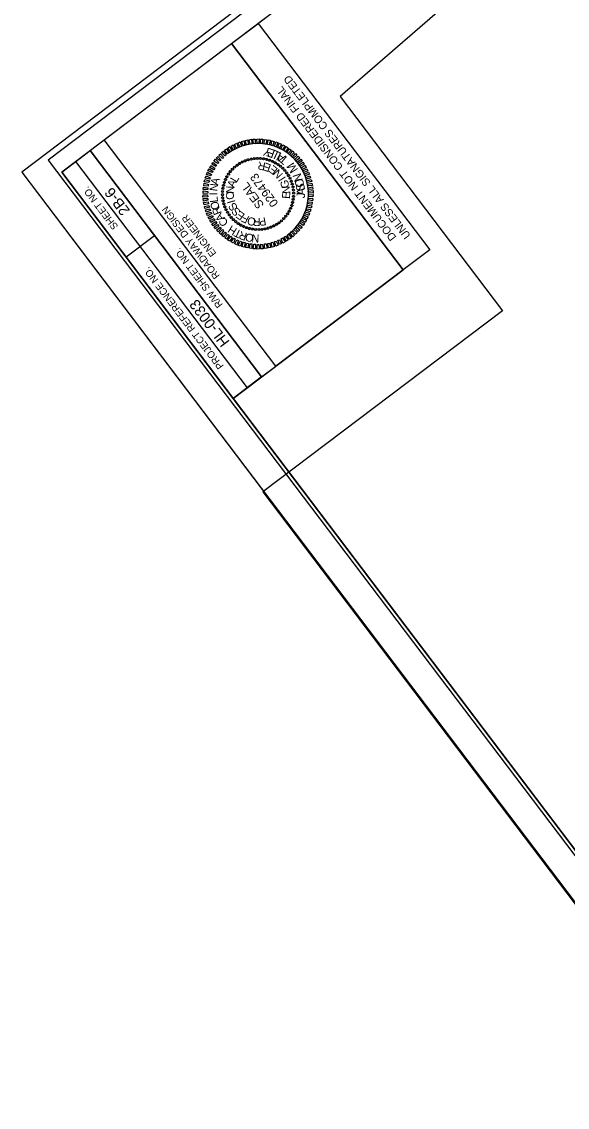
# Model space of a CAD drawing. Extents: x 2046295 to 2051060, y 758814 to 763808.
# Drawn here: x 2046295.2 to 2046525.7, y 759223.6 to 759682.5 of the extents above; entities that cross this region are included whole.
import ezdxf

# ---------------------------------------------------------------- set-up
doc = ezdxf.new("R2010")
doc.units = 0
for name, color, linetype in [('Exist Mkg Skp Wht', 7, 'Continuous'), ('Old_Level_2', 7, 'Continuous'), ('Scratch_Level_0', 7, 'Continuous'), ('Sheet Clip Boundary CELL', 7, 'Continuous'), ('Sheet Cutting Line CELL', 7, 'Continuous'), ('Sheet Data Field CELL', 7, 'Continuous'), ('Sheet Plan CELL', 7, 'Continuous'), ('Sheet Plot Border Inside CELL', 7, 'Continuous'), ('Sheet Plot Border Outside CELL', 7, 'Continuous'), ('Sheet Sticker Exception Certification CELL', 7, 'Continuous')]:
    doc.layers.add(name, color=color, linetype=linetype)

msp = doc.modelspace()

# ---------------------------------------------------------------- linework, layer by layer
at = {"layer": 'Old_Level_2'}
for p, q in [((2046386.22, 759621.85), (2046386.22, 759621.85)), ((2046387.32, 759622.57), (2046387.32, 759622.57)), ((2046388.48, 759623.18), (2046388.48, 759623.18)), ((2046389.64, 759623.73), (2046389.64, 759623.73)), ((2046390.9, 759624.15), (2046390.9, 759624.15)), ((2046392.19, 759624.45), (2046392.19, 759624.45)), ((2046393.48, 759624.67), (2046393.48, 759624.67)), ((2046394.79, 759624.73), (2046394.79, 759624.73)), ((2046396.12, 759624.72), (2046396.12, 759624.72)), ((2046397.41, 759624.56), (2046397.41, 759624.56)), ((2046398.72, 759624.31), (2046398.72, 759624.31)), ((2046399.95, 759623.93), (2046399.95, 759623.93)), ((2046401.19, 759623.44), (2046401.19, 759623.44)), ((2046402.37, 759622.87), (2046402.37, 759622.87)), ((2046403.48, 759622.2), (2046403.48, 759622.2)), ((2046382.57, 759618.07), (2046382.57, 759618.07)), ((2046383.35, 759619.11), (2046383.35, 759619.11)), ((2046384.26, 759620.1), (2046384.26, 759620.1)), ((2046385.18, 759621.03), (2046385.18, 759621.03)), ((2046404.53, 759621.41), (2046404.53, 759621.41)), ((2046405.52, 759620.51), (2046405.52, 759620.51)), ((2046406.44, 759619.59), (2046406.44, 759619.59)), ((2046407.26, 759618.55), (2046407.26, 759618.55)), ((2046407.99, 759617.44), (2046407.99, 759617.44)), ((2046380.45, 759613.31), (2046380.45, 759613.31)), ((2046380.84, 759614.54), (2046380.84, 759614.54)), ((2046381.33, 759615.78), (2046381.33, 759615.78)), ((2046381.9, 759616.96), (2046381.9, 759616.96)), ((2046408.6, 759616.29), (2046408.6, 759616.29)), ((2046409.14, 759615.12), (2046409.14, 759615.12)), ((2046409.57, 759613.86), (2046409.57, 759613.86)), ((2046380.04, 759609.38), (2046380.04, 759609.38)), ((2046380.05, 759610.71), (2046380.05, 759610.71)), ((2046380.09, 759608.07), (2046380.09, 759608.07)), ((2046380.21, 759611.99), (2046380.21, 759611.99)), ((2046395.09, 759609.68), (2046395.09, 759609.68)), ((2046409.86, 759612.58), (2046409.86, 759612.58)), ((2046410.09, 759611.29), (2046410.09, 759611.29)), ((2046410.13, 759608.65), (2046410.13, 759608.65)), ((2046410.14, 759609.97), (2046410.14, 759609.97)), ((2046380.32, 759606.77), (2046380.32, 759606.77)), ((2046380.61, 759605.49), (2046380.61, 759605.49)), ((2046381.04, 759604.23), (2046381.04, 759604.23)), ((2046408.85, 759603.58), (2046408.85, 759603.58)), ((2046409.34, 759604.81), (2046409.34, 759604.81)), ((2046409.73, 759606.05), (2046409.73, 759606.05)), ((2046409.98, 759607.36), (2046409.98, 759607.36)), ((2046381.58, 759603.06), (2046381.58, 759603.06)), ((2046382.2, 759601.91), (2046382.2, 759601.91)), ((2046382.92, 759600.8), (2046382.92, 759600.8)), ((2046383.74, 759599.77), (2046383.74, 759599.77)), ((2046405.92, 759599.25), (2046405.92, 759599.25)), ((2046406.83, 759600.24), (2046406.83, 759600.24)), ((2046407.61, 759601.28), (2046407.61, 759601.28)), ((2046408.28, 759602.39), (2046408.28, 759602.39)), ((2046384.66, 759598.85), (2046384.66, 759598.85)), ((2046385.65, 759597.94), (2046385.65, 759597.94)), ((2046386.7, 759597.15), (2046386.7, 759597.15)), ((2046387.81, 759596.48), (2046387.81, 759596.48)), ((2046388.99, 759595.91), (2046388.99, 759595.91)), ((2046390.23, 759595.42), (2046390.23, 759595.42)), ((2046391.46, 759595.04), (2046391.46, 759595.04)), ((2046392.78, 759594.79), (2046392.78, 759594.79)), ((2046394.06, 759594.64), (2046394.06, 759594.64)), ((2046395.39, 759594.62), (2046395.39, 759594.62)), ((2046396.7, 759594.68), (2046396.7, 759594.68)), ((2046398, 759594.9), (2046398, 759594.9)), ((2046399.28, 759595.2), (2046399.28, 759595.2)), ((2046400.54, 759595.62), (2046400.54, 759595.62)), ((2046401.7, 759596.17), (2046401.7, 759596.17)), ((2046402.86, 759596.78), (2046402.86, 759596.78)), ((2046403.97, 759597.51), (2046403.97, 759597.51)), ((2046405, 759598.33), (2046405, 759598.33))]:
    msp.add_line(p, q, dxfattribs=at)
for points in [[(2046386.05, 759629.02), (2046385.12, 759630.65), (2046386.06, 759631.1), (2046386.7, 759629.21)], [(2046387.43, 759629.58), (2046386.62, 759631.3), (2046387.54, 759631.73), (2046388.08, 759629.77)], [(2046388.85, 759630.09), (2046388.16, 759631.9), (2046389.14, 759632.15), (2046389.56, 759630.21)], [(2046390.27, 759630.41), (2046389.7, 759632.31), (2046390.71, 759632.51), (2046390.98, 759630.57)], [(2046391.73, 759630.76), (2046391.3, 759632.58), (2046392.31, 759632.78), (2046392.4, 759630.82)], [(2046393.19, 759630.97), (2046392.9, 759632.85), (2046393.93, 759632.88), (2046393.91, 759630.91)], [(2046394.69, 759630.97), (2046394.53, 759632.88), (2046395.57, 759632.95), (2046395.38, 759631.01)], [(2046396.15, 759630.94), (2046396.14, 759632.89), (2046397.16, 759632.84), (2046396.83, 759630.94)], [(2046397.69, 759630.8), (2046397.75, 759632.76), (2046398.75, 759632.58), (2046398.36, 759630.7)], [(2046399.12, 759630.64), (2046399.38, 759632.49), (2046400.39, 759632.35), (2046399.8, 759630.44)], [(2046400.59, 759630.25), (2046400.96, 759632.14), (2046401.95, 759631.88), (2046401.24, 759630.03)], [(2046402, 759629.88), (2046402.54, 759631.69), (2046403.47, 759631.41), (2046402.68, 759629.57)], [(2046403.39, 759629.28), (2046404.01, 759631.14), (2046404.96, 759630.69), (2046404.02, 759629.04)], [(2046380.02, 759624.72), (2046378.5, 759626.02), (2046379.26, 759626.7), (2046380.52, 759625.25)], [(2046381.06, 759625.73), (2046379.69, 759627.14), (2046380.46, 759627.8), (2046381.59, 759626.21)], [(2046382.23, 759626.66), (2046380.98, 759628.16), (2046381.8, 759628.77), (2046382.81, 759627.09)], [(2046383.45, 759627.54), (2046382.32, 759629.13), (2046383.14, 759629.68), (2046384.06, 759627.93)], [(2046384.69, 759628.29), (2046383.67, 759629.93), (2046384.56, 759630.45), (2046385.35, 759628.6)], [(2046404.74, 759628.69), (2046405.5, 759630.47), (2046406.4, 759629.98), (2046405.36, 759628.32)], [(2046406.04, 759628.01), (2046406.96, 759629.69), (2046407.79, 759629.19), (2046406.64, 759627.52)], [(2046407.31, 759627.13), (2046408.33, 759628.77), (2046409.11, 759628.19), (2046407.86, 759626.76)], [(2046408.49, 759626.22), (2046409.62, 759627.86), (2046410.4, 759627.18), (2046408.99, 759625.81)], [(2046409.62, 759625.27), (2046410.87, 759626.81), (2046411.53, 759626.08), (2046410.13, 759624.75)], [(2046377.24, 759621.22), (2046375.52, 759622.21), (2046376.06, 759623.04), (2046377.56, 759621.84)], [(2046378.1, 759622.48), (2046376.39, 759623.59), (2046377.07, 759624.33), (2046378.48, 759623.02)], [(2046379.03, 759623.63), (2046377.44, 759624.79), (2046378.14, 759625.55), (2046379.42, 759624.16)], [(2046410.64, 759624.23), (2046411.97, 759625.65), (2046412.68, 759624.91), (2046411.14, 759623.71)], [(2046411.66, 759623.13), (2046413.13, 759624.42), (2046413.7, 759623.61), (2046412.07, 759622.53)], [(2046412.51, 759621.96), (2046414.06, 759623.14), (2046414.64, 759622.33), (2046412.92, 759621.37)], [(2046374.69, 759615.9), (2046372.79, 759616.31), (2046373.14, 759617.29), (2046374.92, 759616.53)], [(2046375.2, 759617.27), (2046373.33, 759617.85), (2046373.7, 759618.84), (2046375.42, 759617.96)], [(2046375.78, 759618.68), (2046373.93, 759619.39), (2046374.43, 759620.26), (2046376.01, 759619.32)], [(2046376.44, 759619.94), (2046374.66, 759620.81), (2046375.19, 759621.7), (2046376.79, 759620.58)], [(2046413.34, 759620.71), (2046414.97, 759621.79), (2046415.42, 759620.89), (2046413.68, 759620.06)], [(2046414.02, 759619.42), (2046415.71, 759620.36), (2046416.19, 759619.48), (2046414.38, 759618.79)], [(2046414.68, 759618), (2046416.41, 759618.93), (2046416.84, 759617.98), (2046414.94, 759617.4)], [(2046415.24, 759616.61), (2046416.99, 759617.38), (2046417.31, 759616.45), (2046415.45, 759615.98)], [(2046374.07, 759612.99), (2046372.17, 759613.17), (2046372.31, 759614.17), (2046374.18, 759613.64)], [(2046374.3, 759614.48), (2046372.39, 759614.76), (2046372.65, 759615.75), (2046374.52, 759615.17)], [(2046415.62, 759615.21), (2046417.55, 759615.8), (2046417.77, 759614.91), (2046415.87, 759614.53)], [(2046415.98, 759613.79), (2046417.85, 759614.26), (2046418.07, 759613.27), (2046416.12, 759613.07)], [(2046416.27, 759612.27), (2046418.12, 759612.66), (2046418.25, 759611.63), (2046416.32, 759611.6)], [(2046373.86, 759608.5), (2046371.83, 759608.29), (2046371.87, 759609.29), (2046373.74, 759609.24)], [(2046373.83, 759610.02), (2046371.85, 759609.91), (2046371.9, 759610.93), (2046373.82, 759610.73)], [(2046373.88, 759611.49), (2046371.9, 759611.53), (2046372.04, 759612.54), (2046373.9, 759612.22)], [(2046416.33, 759610.85), (2046418.35, 759611.07), (2046418.32, 759610.06), (2046416.44, 759610.11)], [(2046416.35, 759609.33), (2046418.34, 759609.44), (2046418.28, 759608.42), (2046416.36, 759608.62)], [(2046373.92, 759607.08), (2046372.06, 759606.69), (2046371.93, 759607.72), (2046373.86, 759607.75)], [(2046374.2, 759605.56), (2046372.34, 759605.09), (2046372.11, 759606.09), (2046374.06, 759606.29)], [(2046374.56, 759604.14), (2046372.64, 759603.55), (2046372.42, 759604.44), (2046374.31, 759604.82)], [(2046415.88, 759604.87), (2046417.79, 759604.59), (2046417.53, 759603.6), (2046415.66, 759604.18)], [(2046416.11, 759606.36), (2046418.01, 759606.19), (2046417.88, 759605.18), (2046416, 759605.71)], [(2046416.3, 759607.86), (2046418.28, 759607.82), (2046418.14, 759606.81), (2046416.28, 759607.13)], [(2046374.94, 759602.74), (2046373.19, 759601.97), (2046372.87, 759602.9), (2046374.73, 759603.37)], [(2046375.5, 759601.36), (2046373.77, 759600.42), (2046373.34, 759601.38), (2046375.24, 759601.95)], [(2046376.16, 759599.94), (2046374.47, 759598.99), (2046373.99, 759599.87), (2046375.8, 759600.56)], [(2046376.84, 759598.64), (2046375.21, 759597.56), (2046374.76, 759598.46), (2046376.5, 759599.29)], [(2046413.74, 759599.41), (2046415.52, 759598.54), (2046414.99, 759597.65), (2046413.39, 759598.77)], [(2046414.4, 759600.67), (2046416.25, 759599.96), (2046415.75, 759599.09), (2046414.17, 759600.04)], [(2046414.99, 759602.09), (2046416.85, 759601.51), (2046416.48, 759600.51), (2046414.76, 759601.39)], [(2046415.49, 759603.45), (2046417.39, 759603.04), (2046417.04, 759602.06), (2046415.26, 759602.82)], [(2046377.67, 759597.39), (2046376.12, 759596.22), (2046375.55, 759597.02), (2046377.26, 759597.99)], [(2046378.52, 759596.23), (2046377.06, 759594.93), (2046376.48, 759595.74), (2046378.11, 759596.82)], [(2046379.54, 759595.12), (2046378.21, 759593.7), (2046377.5, 759594.44), (2046379.04, 759595.64)], [(2046380.56, 759594.08), (2046379.32, 759592.54), (2046378.65, 759593.28), (2046380.05, 759594.6)], [(2046410.16, 759594.64), (2046411.68, 759593.33), (2046410.92, 759592.65), (2046409.66, 759594.11)], [(2046411.15, 759595.72), (2046412.75, 759594.56), (2046412.04, 759593.8), (2046410.76, 759595.2)], [(2046412.08, 759596.88), (2046413.79, 759595.76), (2046413.11, 759595.02), (2046411.71, 759596.33)], [(2046412.94, 759598.13), (2046414.67, 759597.14), (2046414.12, 759596.32), (2046412.62, 759597.51)], [(2046381.69, 759593.13), (2046380.56, 759591.49), (2046379.78, 759592.18), (2046381.19, 759593.54)], [(2046382.87, 759592.22), (2046381.85, 759590.58), (2046381.07, 759591.16), (2046382.32, 759592.6)], [(2046384.14, 759591.34), (2046383.22, 759589.67), (2046382.39, 759590.17), (2046383.54, 759591.83)], [(2046385.44, 759590.67), (2046384.68, 759588.89), (2046383.78, 759589.37), (2046384.82, 759591.03)], [(2046386.79, 759590.07), (2046386.17, 759588.21), (2046385.23, 759588.66), (2046386.16, 759590.31)], [(2046388.19, 759589.47), (2046387.64, 759587.66), (2046386.71, 759587.94), (2046387.5, 759589.78)], [(2046402.75, 759589.77), (2046403.56, 759588.05), (2046402.64, 759587.62), (2046402.1, 759589.58)], [(2046404.13, 759590.33), (2046405.06, 759588.7), (2046404.12, 759588.25), (2046403.48, 759590.14)], [(2046405.49, 759591.06), (2046406.51, 759589.42), (2046405.62, 759588.9), (2046404.83, 759590.75)], [(2046406.73, 759591.81), (2046407.86, 759590.22), (2046407.04, 759589.67), (2046406.12, 759591.43)], [(2046407.95, 759592.69), (2046409.2, 759591.19), (2046408.38, 759590.58), (2046407.37, 759592.26)], [(2046409.13, 759593.62), (2046410.49, 759592.21), (2046409.72, 759591.55), (2046408.59, 759593.14)], [(2046389.59, 759589.11), (2046389.22, 759587.21), (2046388.23, 759587.47), (2046388.94, 759589.33)], [(2046391.06, 759588.71), (2046390.8, 759586.86), (2046389.79, 759587), (2046390.38, 759588.91)], [(2046392.49, 759588.56), (2046392.44, 759586.59), (2046391.43, 759586.78), (2046391.82, 759588.65)], [(2046394.03, 759588.41), (2046394.04, 759586.46), (2046393.02, 759586.51), (2046393.35, 759588.42)], [(2046395.49, 759588.38), (2046395.65, 759586.47), (2046394.61, 759586.4), (2046394.8, 759588.34)], [(2046396.99, 759588.38), (2046397.28, 759586.5), (2046396.25, 759586.47), (2046396.27, 759588.44)], [(2046398.45, 759588.59), (2046398.88, 759586.77), (2046397.87, 759586.57), (2046397.78, 759588.53)], [(2046399.91, 759588.94), (2046400.49, 759587.04), (2046399.47, 759586.84), (2046399.21, 759588.78)], [(2046401.33, 759589.26), (2046402.02, 759587.45), (2046401.04, 759587.2), (2046400.63, 759589.14)]]:
    msp.add_lwpolyline(points, close=True, dxfattribs=at)
for centre, major_axis in [((2046386.22, 759621.83), (-0.255, 0.349)), ((2046387.31, 759622.56), (-0.223, 0.37)), ((2046388.46, 759623.19), (-0.19, 0.388)), ((2046389.67, 759623.71), (-0.156, 0.403)), ((2046390.91, 759624.13), (-0.12, 0.415)), ((2046392.19, 759624.44), (-0.083, 0.424)), ((2046393.48, 759624.64), (-0.046, 0.43)), ((2046394.79, 759624.72), (-0.009, 0.432)), ((2046396.11, 759624.69), (0.029, 0.431)), ((2046397.41, 759624.54), (0.067, 0.427)), ((2046398.7, 759624.29), (0.104, 0.419)), ((2046399.96, 759623.92), (0.14, 0.409)), ((2046401.18, 759623.44), (0.175, 0.395)), ((2046402.36, 759622.85), (0.209, 0.378)), ((2046403.48, 759622.17), (0.241, 0.359)), ((2046404.53, 759621.39), (0.271, 0.336)), ((2046381.91, 759616.94), (-0.378, 0.209)), ((2046382.6, 759618.06), (-0.359, 0.241)), ((2046383.37, 759619.12), (-0.336, 0.271)), ((2046384.24, 759620.1), (-0.311, 0.299)), ((2046385.19, 759621.01), (-0.284, 0.325)), ((2046405.52, 759620.52), (0.299, 0.311)), ((2046406.43, 759619.57), (0.325, 0.284)), ((2046407.24, 759618.55), (0.349, 0.255)), ((2046407.97, 759617.46), (0.37, 0.223)), ((2046380.48, 759613.28), (-0.419, 0.104)), ((2046380.85, 759614.54), (-0.409, 0.14)), ((2046381.33, 759615.77), (-0.395, 0.175)), ((2046408.6, 759616.3), (0.388, 0.19)), ((2046409.13, 759615.1), (0.403, 0.156)), ((2046409.55, 759613.86), (0.415, 0.12)), ((2046409.86, 759612.58), (0.424, 0.083)), ((2046380.05, 759609.38), (-0.432, -0.009)), ((2046380.08, 759610.69), (-0.431, 0.029)), ((2046380.13, 759608.07), (-0.43, -0.046)), ((2046380.22, 759612), (-0.427, 0.067)), ((2046410.05, 759611.28), (0.43, 0.046)), ((2046410.1, 759608.66), (0.431, -0.029)), ((2046410.14, 759609.97), (0.432, 0.009)), ((2046380.33, 759606.77), (-0.424, -0.083)), ((2046380.63, 759605.5), (-0.415, -0.12)), ((2046381.05, 759604.25), (-0.403, -0.156)), ((2046381.58, 759603.05), (-0.388, -0.19)), ((2046408.85, 759603.59), (0.395, -0.175)), ((2046409.33, 759604.81), (0.409, -0.14)), ((2046409.7, 759606.07), (0.419, -0.104)), ((2046409.96, 759607.36), (0.427, -0.067)), ((2046382.21, 759601.9), (-0.37, -0.223)), ((2046382.94, 759600.8), (-0.349, -0.255)), ((2046383.76, 759599.78), (-0.325, -0.284)), ((2046384.66, 759598.83), (-0.299, -0.311)), ((2046405.94, 759599.25), (0.311, -0.299)), ((2046406.81, 759600.23), (0.336, -0.271)), ((2046407.58, 759601.29), (0.359, -0.241)), ((2046408.27, 759602.41), (0.378, -0.209)), ((2046385.65, 759597.96), (-0.271, -0.336)), ((2046386.7, 759597.18), (-0.241, -0.359)), ((2046387.82, 759596.5), (-0.209, -0.378)), ((2046389, 759595.92), (-0.175, -0.395)), ((2046390.22, 759595.44), (-0.14, -0.409)), ((2046391.48, 759595.07), (-0.104, -0.419)), ((2046392.77, 759594.81), (-0.067, -0.427)), ((2046394.07, 759594.66), (-0.029, -0.431)), ((2046395.39, 759594.63), (0.009, -0.432)), ((2046396.7, 759594.71), (0.046, -0.43)), ((2046398, 759594.91), (0.083, -0.424)), ((2046399.27, 759595.22), (0.12, -0.415)), ((2046400.51, 759595.64), (0.156, -0.403)), ((2046401.72, 759596.17), (0.19, -0.388)), ((2046402.87, 759596.79), (0.223, -0.37)), ((2046403.96, 759597.52), (0.255, -0.349)), ((2046404.99, 759598.34), (0.284, -0.325))]:
    msp.add_ellipse(centre, major_axis=major_axis, ratio=0.999708, dxfattribs=at)
at = {"layer": 'Scratch_Level_0'}
msp.add_arc((2046395.09, 759609.68), 21.3, 307.1294, 127.1294, dxfattribs=at)
at = {"layer": 'Sheet Clip Boundary CELL'}
msp.add_lwpolyline([(2046947.67, 758972.8), (2047186.85, 759153.88), (2047203.68, 759209.07), (2047315.83, 759293.98), (2046807.51, 759978.36), (2046429.78, 759650.86), (2046498.33, 759560.32), (2046397.16, 759483.72), (2046835.66, 758904.54)], close=True, dxfattribs=at)
at = {"layer": 'Sheet Cutting Line CELL'}
msp.add_line((2046295.24, 759618.91), (2046904.95, 758813.59), dxfattribs=at)
at = {"layer": 'Sheet Plan CELL'}
for p, q in [((2046396.6, 759532.31), (2046324.14, 759627.99)), ((2046396.6, 759532.31), (2046324.14, 759627.99)), ((2046390.61, 759527.76), (2046318.16, 759623.46)), ((2046339.36, 759583.05), (2046351.3, 759592.13)), ((2046396.6, 759532.31), (2046402.57, 759536.83))]:
    msp.add_line(p, q, dxfattribs=at)
for points in [[(2046312.14, 759618.94), (2046855.41, 758901.37), (2047357.69, 759281.65), (2046814.43, 759999.2)], [(2047357.69, 759281.65), (2046855.43, 758901.37), (2046384.6, 759523.22), (2046456.38, 759577.58), (2046383.94, 759673.27), (2046814.43, 759999.2)], [(2046402.57, 759536.83), (2046330.12, 759632.52), (2046383.94, 759673.27), (2046456.38, 759577.58)], [(2046384.6, 759523.22), (2046312.14, 759618.94), (2046324.14, 759627.99), (2046396.6, 759532.31)]]:
    msp.add_lwpolyline(points, close=True, dxfattribs=at)
at = {"layer": 'Sheet Plot Border Inside CELL'}
msp.add_lwpolyline([(2047414.48, 759209.14), (2046811.11, 760006.08), (2046306.43, 759624), (2046909.81, 758827.05)], close=True, dxfattribs=at)
at = {"layer": 'Sheet Plot Border Outside CELL'}
msp.add_lwpolyline([(2047428.76, 759210.16), (2046819.05, 760015.49), (2046295.24, 759618.91), (2046904.95, 758813.59)], close=True, dxfattribs=at)
at = {"layer": 'Sheet Sticker Exception Certification CELL'}
for p, q in [((2046383.94, 759673.27), (2046395.18, 759681.78)), ((2046383.94, 759673.27), (2046395.18, 759681.78)), ((2046395.17, 759681.78), (2046467.62, 759586.09)), ((2046395.17, 759681.78), (2046467.62, 759586.09)), ((2046456.38, 759577.58), (2046383.93, 759673.27)), ((2046456.38, 759577.58), (2046383.93, 759673.27)), ((2046467.62, 759586.09), (2046456.38, 759577.58)), ((2046467.62, 759586.09), (2046456.38, 759577.58))]:
    msp.add_line(p, q, dxfattribs=at)

# ---------------------------------------------------------------- texts
at = {"layer": 'Exist Mkg Skp Wht'}
for s, rotation, p in [('Y', 164.424, (2046401.02, 759628.64)), ('E', 159.5982, (2046402.59, 759628.07)), ('L', 155.3389, (2046403.94, 759627.47)), ('L', 151.0796, (2046405.24, 759626.76)), ('A', 145.0789, (2046406.97, 759625.61)), ('T', 140.4629, (2046408.21, 759624.6)), ('M', 122.9746, (2046412.09, 759619.97)), ('.', 130.8008, (2046410.53, 759622.18)), ('N', 108.77, (2046414.09, 759615.48)), ('O', 100.9229, (2046414.71, 759612.83)), ('S', 95.9502, (2046414.91, 759611.12)), ('J', 86.3805, (2046414.87, 759607.8)), ('A', 89.9494, (2046414.95, 759609.04))]:
    msp.add_text(s, height=3.6, rotation=rotation, dxfattribs=at).set_placement(p)
at = {"layer": 'Old_Level_2'}
for s, height, rotation, p in [('R', 3.38, 169.6108, (2046398.47, 759622.85)), ('E', 3.38, 160.2535, (2046400.88, 759622)), ('E', 3.38, 141.5412, (2046403.74, 759620.17)), ('029473', 3.6, 126.1294, (2046403.83, 759605.79)), ('N', 3.38, 132.1858, (2046405.82, 759618.02)), ('N', 3.38, 82.9483, (2046377.86, 759610.67)), ('A', 3.38, 75.7466, (2046378.2, 759613.15)), ('N', 3.38, 87.6061, (2046384.85, 759609.79)), ('A', 3.38, 68.8897, (2046385.06, 759612.09)), ('L', 3.38, 59.5303, (2046386, 759614.27)), ('SEAL', 3.599, 126.1294, (2046397.82, 759605.08)), ('I', 3.38, 122.8306, (2046406.96, 759616.37)), ('G', 3.38, 104.1197, (2046408.42, 759612.54)), ('N', 3.38, 94.7634, (2046408.72, 759609.91)), ('I', 3.38, 90.1496, (2046377.9, 759609.08)), ('L', 3.38, 97.3503, (2046378.22, 759606.27)), ('O', 3.38, 96.9629, (2046385.1, 759607.46)), ('E', 3.38, 85.4063, (2046408.52, 759607.5)), ('O', 3.38, 104.5506, (2046378.92, 759603.49)), ('R', 3.38, 111.7505, (2046379.78, 759601.62)), ('I', 3.38, 106.319, (2046385.49, 759606.25)), ('S', 3.38, 125.0298, (2046386.72, 759603.94)), ('S', 3.38, 134.385, (2046388.04, 759602.23)), ('A', 3.38, 126.1498, (2046381.2, 759599.54)), ('C', 3.38, 133.3493, (2046382.78, 759597.76)), ('E', 3.38, 143.7405, (2046389.8, 759600.96)), ('F', 3.38, 153.0965, (2046391.67, 759599.98)), ('O', 3.38, 171.8107, (2046394.28, 759599.47)), ('R', 3.38, 181.1691, (2046396.08, 759599.52)), ('P', 3.38, 190.5283, (2046398.19, 759599.91)), ('H', 3.38, 147.7489, (2046386.49, 759594.85)), ('T', 3.38, 154.9492, (2046388.45, 759593.89)), ('R', 3.38, 162.1499, (2046390.74, 759593.06)), ('O', 3.38, 169.3512, (2046393.47, 759592.53)), ('N', 3.38, 176.5529, (2046395.69, 759592.48))]:
    msp.add_text(s, height=height, rotation=rotation, dxfattribs=at).set_placement(p)
at = {"layer": 'Sheet Data Field CELL'}
for s, p in [('2B-6', (2046341.16, 759602.72)), ('HL-0033  ', (2046383.26, 759547.18))]:
    msp.add_text(s, height=4.5, rotation=127.1294, dxfattribs=at).set_placement(p)
at = {"layer": 'Sheet Plan CELL'}
for s, height, p in [('SHEET NO.', 3, (2046336.18, 759595.96)), ('ROADWAY DESIGN', 3.0001, (2046379.08, 759575.12)), ('ENGINEER', 3, (2046377.62, 759584.54)), ('R/W SHEET NO.', 3.0001, (2046380.35, 759562.9)), ('PROJECT REFERENCE NO.', 3.0001, (2046380.73, 759537))]:
    msp.add_text(s, height=height, rotation=127.1294, dxfattribs=at).set_placement(p)
at = {"layer": 'Sheet Sticker Exception Certification CELL'}
for s, p in [('UNLESS ALL SIGNATURES COMPLETED', (2046459.74, 759592.16)), ('UNLESS ALL SIGNATURES COMPLETED', (2046459.74, 759592.16)), ('DOCUMENT NOT CONSIDERED FINAL', (2046453.69, 759591.4)), ('DOCUMENT NOT CONSIDERED FINAL', (2046453.69, 759591.4))]:
    msp.add_text(s, height=3.3, rotation=127.1294, dxfattribs=at).set_placement(p)

doc.saveas('drawing.dxf')
